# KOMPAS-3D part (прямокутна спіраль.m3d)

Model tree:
1. Эскиз:1
2. Поверхность выдавливания:1
     Расстояние 1 = 100; Расстояние 2 = 10
3. Эскиз:2
4. Спираль цилиндрическая:1
     Число витков = 20; Шаг = 5; Размер = 100; Диаметр 1 = 10; Диаметр 2 = 10
5. Эскиз:3
6. Спираль цилиндрическая:2
     Число витков = 20; Шаг = 5; Размер = 100; Диаметр 1 = 130; Диаметр 2 = 10
7. Линейчатая поверхность:1
8. Кривая пересечения:1
9. Перпендикулярная плоскость:1
10. Эскиз:4
11. Кинематическая операция:1
     Толщина стенки 1 = 1; Толщина стенки 2 = 1
